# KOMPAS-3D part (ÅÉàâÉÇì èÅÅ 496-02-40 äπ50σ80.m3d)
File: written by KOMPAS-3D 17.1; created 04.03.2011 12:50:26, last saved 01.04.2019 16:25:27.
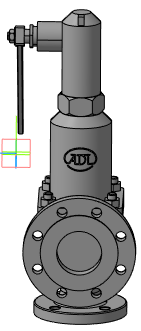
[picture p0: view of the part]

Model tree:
1. Операция без истории:1

Referenced files in C:\Users\tra\Desktop\Детали с марк. для Сферы\bsv\Desktop\Si 57\: VIC_496_50x80_3d.a3d
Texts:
  Viktor2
